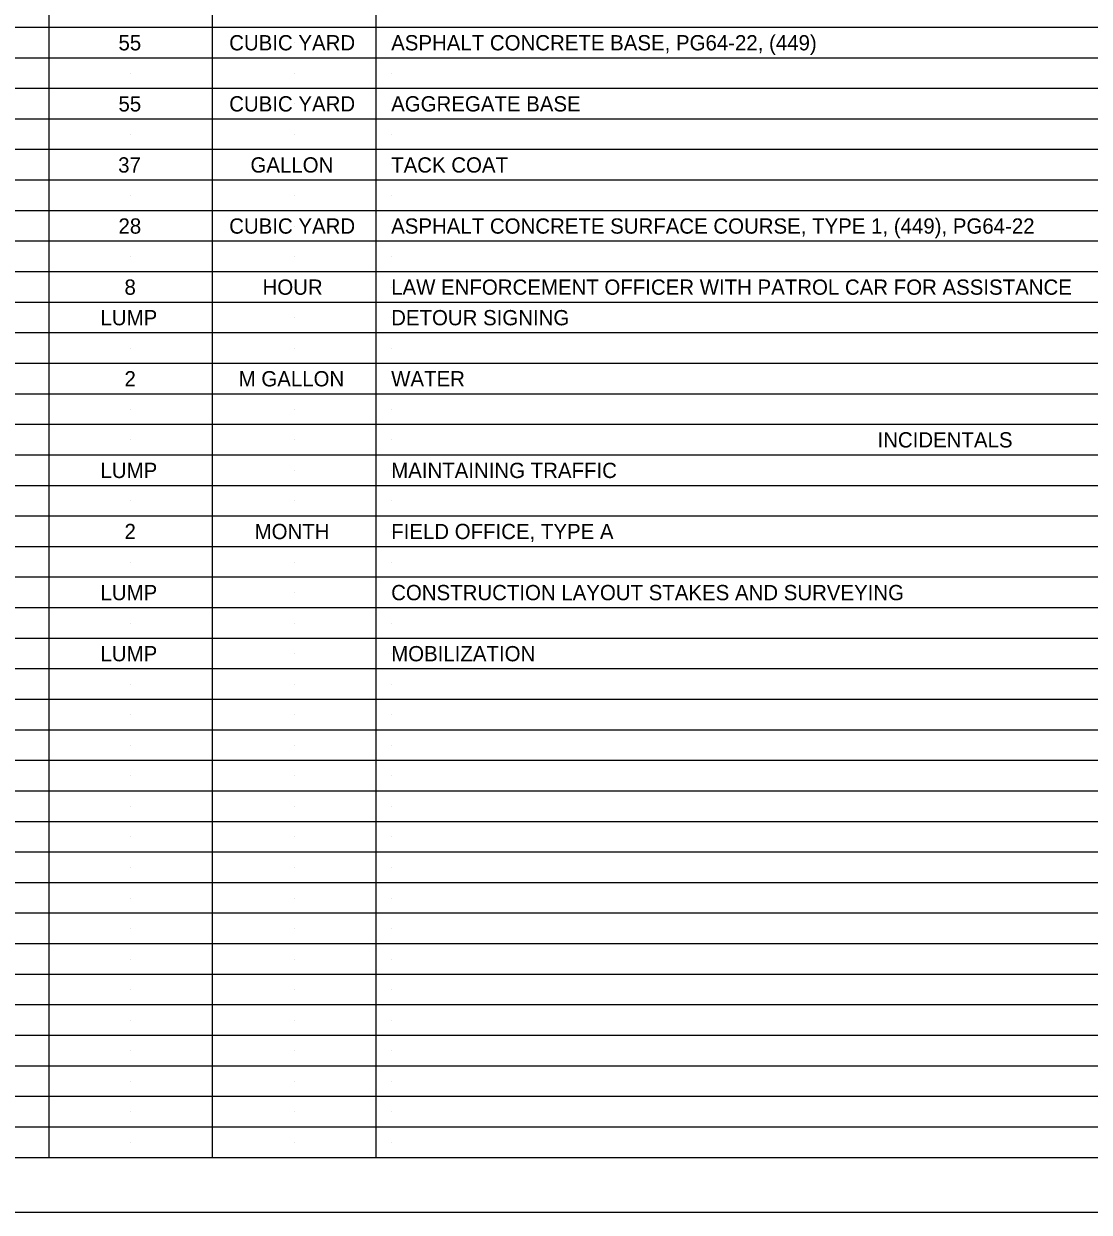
# Model space of a CAD drawing. Extents: x 0 to 34, y 0 to 22.
# Drawn here: x 17.27 to 27.04, y 0 to 10.89 of the extents above; entities that cross this region are included whole.
import ezdxf

# ---------------------------------------------------------------- set-up
doc = ezdxf.new("R2010")
doc.units = 0
for name, color, linetype in [('RD_P_Text', 7, 'Continuous'), ('SC_Scratch1', 7, 'Continuous'), ('SH_Border', 7, 'Continuous'), ('SH_Cut_Line', 7, 'Continuous'), ('SH_Data', 7, 'Continuous')]:
    doc.layers.add(name, color=color, linetype=linetype)

msp = doc.modelspace()

# ---------------------------------------------------------------- linework, layer by layer
at = {"layer": 'SC_Scratch1'}
for p, q in [((18.25, 10.72), (18.25, 10.72)), ((19.75, 10.72), (19.75, 10.72)), ((20.64, 10.72), (20.64, 10.72)), ((18.25, 10.44), (18.25, 10.44)), ((19.75, 10.44), (19.75, 10.44)), ((20.64, 10.44), (20.64, 10.44)), ((18.25, 10.16), (18.25, 10.16)), ((19.75, 10.16), (19.75, 10.16)), ((20.64, 10.16), (20.64, 10.16)), ((18.25, 9.88), (18.25, 9.88)), ((19.75, 9.88), (19.75, 9.88)), ((20.64, 9.88), (20.64, 9.88)), ((18.25, 9.6), (18.25, 9.6)), ((19.75, 9.6), (19.75, 9.6)), ((20.64, 9.6), (20.64, 9.6)), ((18.25, 9.32), (18.25, 9.32)), ((19.75, 9.32), (19.75, 9.32)), ((20.64, 9.32), (20.64, 9.32)), ((18.25, 9.04), (18.25, 9.04)), ((19.75, 9.04), (19.75, 9.04)), ((20.64, 9.04), (20.64, 9.04)), ((18.25, 8.76), (18.25, 8.76)), ((19.75, 8.76), (19.75, 8.76)), ((20.64, 8.76), (20.64, 8.76)), ((18.25, 8.48), (18.25, 8.48)), ((19.75, 8.48), (19.75, 8.48)), ((20.64, 8.48), (20.64, 8.48)), ((18.25, 8.2), (18.25, 8.2)), ((19.75, 8.2), (19.75, 8.2)), ((20.64, 8.2), (20.64, 8.2)), ((18.25, 7.92), (18.25, 7.92)), ((19.75, 7.92), (19.75, 7.92)), ((20.64, 7.92), (20.64, 7.92)), ((18.25, 7.64), (18.25, 7.64)), ((19.75, 7.64), (19.75, 7.64)), ((20.64, 7.64), (20.64, 7.64)), ((18.25, 7.36), (18.25, 7.36)), ((19.75, 7.36), (19.75, 7.36)), ((20.64, 7.36), (20.64, 7.36)), ((18.25, 7.08), (18.25, 7.08)), ((19.75, 7.08), (19.75, 7.08)), ((20.64, 7.08), (20.64, 7.08)), ((18.25, 6.8), (18.25, 6.8)), ((19.75, 6.8), (19.75, 6.8)), ((20.64, 6.8), (20.64, 6.8)), ((18.25, 6.52), (18.25, 6.52)), ((19.75, 6.52), (19.75, 6.52)), ((20.64, 6.52), (20.64, 6.52)), ((18.25, 6.24), (18.25, 6.24)), ((19.75, 6.24), (19.75, 6.24)), ((20.64, 6.24), (20.64, 6.24)), ((18.25, 5.96), (18.25, 5.96)), ((19.75, 5.96), (19.75, 5.96)), ((20.64, 5.96), (20.64, 5.96)), ((18.25, 5.68), (18.25, 5.68)), ((19.75, 5.68), (19.75, 5.68)), ((20.64, 5.68), (20.64, 5.68)), ((18.25, 5.4), (18.25, 5.4)), ((19.75, 5.4), (19.75, 5.4)), ((20.64, 5.4), (20.64, 5.4)), ((18.25, 5.12), (18.25, 5.12)), ((19.75, 5.12), (19.75, 5.12)), ((20.64, 5.12), (20.64, 5.12)), ((18.25, 4.84), (18.25, 4.84)), ((19.75, 4.84), (19.75, 4.84)), ((20.64, 4.84), (20.64, 4.84)), ((18.25, 4.56), (18.25, 4.56)), ((19.75, 4.56), (19.75, 4.56)), ((20.64, 4.56), (20.64, 4.56)), ((18.25, 4.28), (18.25, 4.28)), ((19.75, 4.28), (19.75, 4.28)), ((20.64, 4.28), (20.64, 4.28)), ((18.25, 4), (18.25, 4)), ((19.75, 4), (19.75, 4)), ((20.64, 4), (20.64, 4)), ((18.25, 3.72), (18.25, 3.72)), ((19.75, 3.72), (19.75, 3.72)), ((20.64, 3.72), (20.64, 3.72)), ((18.25, 3.44), (18.25, 3.44)), ((19.75, 3.44), (19.75, 3.44)), ((20.64, 3.44), (20.64, 3.44)), ((18.25, 3.16), (18.25, 3.16)), ((19.75, 3.16), (19.75, 3.16)), ((20.64, 3.16), (20.64, 3.16)), ((18.25, 2.88), (18.25, 2.88)), ((19.75, 2.88), (19.75, 2.88)), ((20.64, 2.88), (20.64, 2.88)), ((18.25, 2.6), (18.25, 2.6)), ((19.75, 2.6), (19.75, 2.6)), ((20.64, 2.6), (20.64, 2.6)), ((18.25, 2.32), (18.25, 2.32)), ((19.75, 2.32), (19.75, 2.32)), ((20.64, 2.32), (20.64, 2.32)), ((18.25, 2.04), (18.25, 2.04)), ((19.75, 2.04), (19.75, 2.04)), ((20.64, 2.04), (20.64, 2.04)), ((18.25, 1.76), (18.25, 1.76)), ((19.75, 1.76), (19.75, 1.76)), ((20.64, 1.76), (20.64, 1.76)), ((18.25, 1.48), (18.25, 1.48)), ((19.75, 1.48), (19.75, 1.48)), ((20.64, 1.48), (20.64, 1.48)), ((18.25, 1.2), (18.25, 1.2)), ((19.75, 1.2), (19.75, 1.2)), ((20.64, 1.2), (20.64, 1.2)), ((18.25, 0.92), (18.25, 0.92)), ((19.75, 0.92), (19.75, 0.92)), ((20.64, 0.92), (20.64, 0.92)), ((18.25, 0.64), (18.25, 0.64)), ((19.75, 0.64), (19.75, 0.64)), ((20.64, 0.64), (20.64, 0.64))]:
    msp.add_line(p, q, dxfattribs=at)
at = {"layer": 'SH_Border'}
msp.add_lwpolyline([(1.5, 21.5), (33.5, 21.5), (33.5, 0.5), (1.5, 0.5)], close=True, dxfattribs=at)
at = {"layer": 'SH_Cut_Line'}
msp.add_lwpolyline([(0, 0), (34, 0), (34, 22), (0, 22)], close=True, dxfattribs=at)
at = {"layer": 'SH_Data'}
for p, q in [((17.5, 21.5), (17.5, 0.5)), ((19, 21.5), (19, 0.5)), ((20.5, 21.5), (20.5, 0.5)), ((32, 10.86), (1.5, 10.86)), ((32, 10.58), (1.5, 10.58)), ((32, 10.3), (1.5, 10.3)), ((32, 10.02), (1.5, 10.02)), ((32, 9.74), (1.5, 9.74)), ((32, 9.46), (1.5, 9.46)), ((32, 9.18), (1.5, 9.18)), ((32, 8.9), (1.5, 8.9)), ((32, 8.62), (1.5, 8.62)), ((32, 8.34), (1.5, 8.34)), ((32, 8.06), (1.5, 8.06)), ((32, 7.78), (1.5, 7.78)), ((32, 7.5), (1.5, 7.5)), ((32, 7.22), (1.5, 7.22)), ((32, 6.94), (1.5, 6.94)), ((32, 6.66), (1.5, 6.66)), ((32, 6.38), (1.5, 6.38)), ((32, 6.1), (1.5, 6.1)), ((32, 5.82), (1.5, 5.82)), ((32, 5.54), (1.5, 5.54)), ((32, 5.26), (1.5, 5.26)), ((32, 4.98), (1.5, 4.98)), ((32, 4.7), (1.5, 4.7)), ((32, 4.42), (1.5, 4.42)), ((32, 4.14), (1.5, 4.14)), ((32, 3.86), (1.5, 3.86)), ((32, 3.58), (1.5, 3.58)), ((32, 3.3), (1.5, 3.3)), ((32, 3.02), (1.5, 3.02)), ((32, 2.74), (1.5, 2.74)), ((32, 2.46), (1.5, 2.46)), ((32, 2.18), (1.5, 2.18)), ((32, 1.9), (1.5, 1.9)), ((32, 1.62), (1.5, 1.62)), ((32, 1.34), (1.5, 1.34)), ((32, 1.06), (1.5, 1.06)), ((32, 0.78), (1.5, 0.78))]:
    msp.add_line(p, q, dxfattribs=at)

# ---------------------------------------------------------------- texts
at = {"layer": 'RD_P_Text'}
for s, p in [('55', (18.14, 10.65)), ('CUBIC YARD', (19.155, 10.65)), ('ASPHALT CONCRETE BASE, PG64-22, (449)', (20.64, 10.65)), ('55', (18.14, 10.09)), ('CUBIC YARD', (19.155, 10.09)), ('AGGREGATE BASE', (20.64, 10.09)), ('37', (18.137, 9.53)), ('GALLON', (19.35, 9.53)), ('TACK COAT', (20.64, 9.53)), ('28', (18.14, 8.97)), ('CUBIC YARD', (19.155, 8.97)), ('ASPHALT CONCRETE SURFACE COURSE, TYPE 1, (449), PG64-22', (20.64, 8.97)), ('8', (18.195, 8.41)), ('HOUR', (19.461, 8.41)), ('LAW ENFORCEMENT OFFICER WITH PATROL CAR FOR ASSISTANCE', (20.64, 8.41)), ('LUMP', (17.975, 8.13)), ('DETOUR SIGNING', (20.64, 8.13)), ('2', (18.195, 7.57)), ('M GALLON', (19.242, 7.57)), ('WATER', (20.64, 7.57)), ('INCIDENTALS', (25.099, 7.01)), ('LUMP', (17.975, 6.73)), ('MAINTAINING TRAFFIC', (20.64, 6.73)), ('2', (18.195, 6.17)), ('MONTH', (19.388, 6.17)), ('FIELD OFFICE, TYPE A', (20.64, 6.17)), ('LUMP', (17.975, 5.61)), ('CONSTRUCTION LAYOUT STAKES AND SURVEYING', (20.64, 5.61)), ('LUMP', (17.975, 5.05)), ('MOBILIZATION', (20.64, 5.05))]:
    msp.add_text(s, height=0.14, dxfattribs=at).set_placement(p)

doc.saveas('drawing.dxf')
